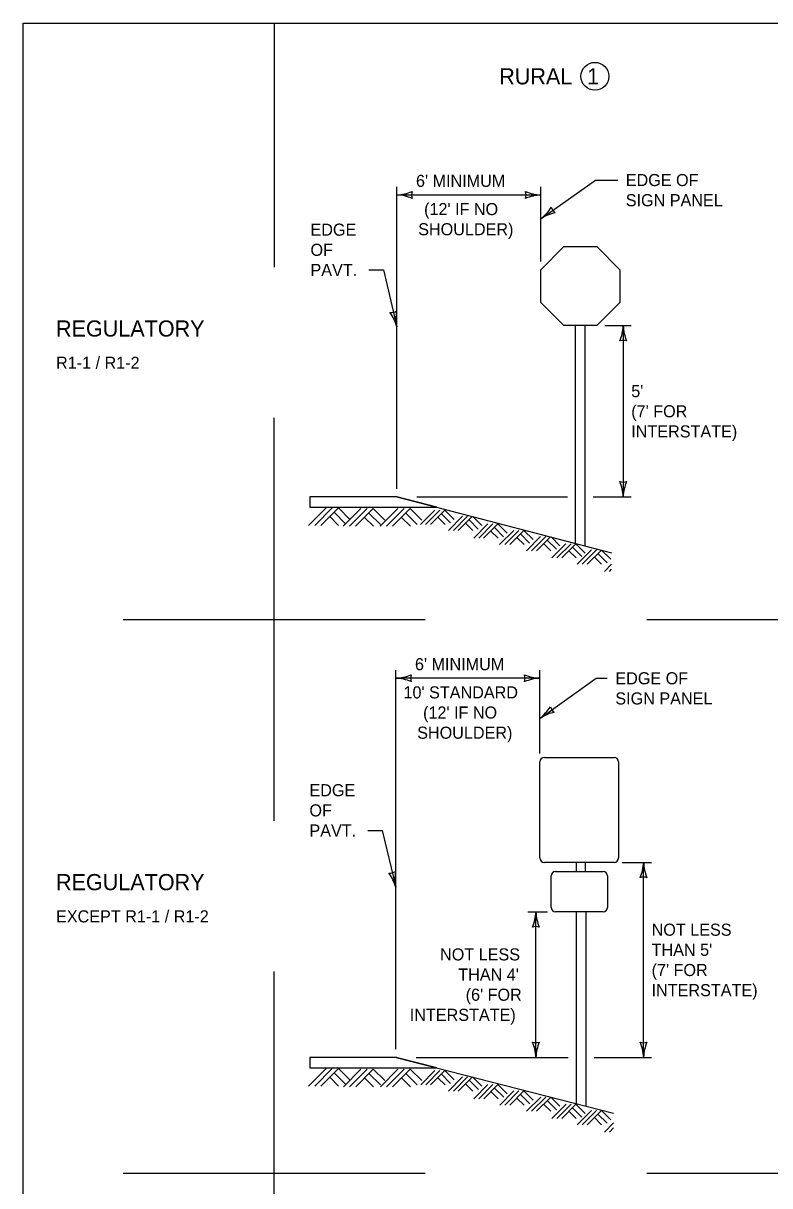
# Model space of a CAD drawing. Extents: x 49991.4 to 50021, y 49987.6 to 50011.4.
# Drawn here: x 49999.38 to 50003.09, y 49993.23 to 49999 of the extents above; entities that cross this region are included whole.
import ezdxf

# ---------------------------------------------------------------- set-up
doc = ezdxf.new("R2010")
doc.units = 0
for name, color, linetype in [('Level 1', 7, 'Continuous'), ('Level 2', 7, 'Continuous'), ('Level 3', 7, 'Continuous')]:
    doc.layers.add(name, color=color, linetype=linetype)

msp = doc.modelspace()

# ---------------------------------------------------------------- linework, layer by layer
at = {"layer": 'Level 1'}
for p, q in [((50002.124, 49996.4185), (50002.124, 49997.4987)), ((50002.1727, 49996.4059), (50002.1727, 49997.4987)), ((50001.2375, 49996.649), (50000.8056, 49996.649)), ((50000.8056, 49996.649), (50000.8056, 49996.5973)), ((50001.2374, 49996.649), (50000.8056, 49996.649)), ((50000.8056, 49996.649), (50000.8056, 49996.5973)), ((50001.2374, 49996.649), (50002.3037, 49996.3718)), ((50001.4363, 49996.5973), (50001.2374, 49996.649)), ((50000.7994, 49996.5068), (50000.8867, 49996.5941)), ((50000.8056, 49996.5973), (50001.4363, 49996.5973)), ((50000.8056, 49996.5973), (50001.4363, 49996.5973)), ((50000.83, 49996.5068), (50000.9173, 49996.5941)), ((50000.8605, 49996.5068), (50000.9477, 49996.5941)), ((50000.9046, 49996.5508), (50000.9488, 49996.5068)), ((50000.9263, 49996.5725), (50000.983, 49996.5158)), ((50000.9477, 49996.5941), (50001.0046, 49996.5373)), ((50000.9721, 49996.5031), (50001.0594, 49996.5905)), ((50001.0027, 49996.5031), (50001.0901, 49996.5905)), ((50001.0332, 49996.5031), (50001.1206, 49996.5905)), ((50001.0774, 49996.5471), (50001.1215, 49996.5031)), ((50001.099, 49996.5688), (50001.1558, 49996.5122)), ((50001.1206, 49996.5905), (50001.1774, 49996.5336)), ((50001.1556, 49996.5031), (50001.2429, 49996.5905)), ((50001.1863, 49996.5031), (50001.2736, 49996.5905)), ((50001.2167, 49996.5031), (50001.3041, 49996.5905)), ((50001.2608, 49996.5471), (50001.305, 49996.5031)), ((50001.2825, 49996.5688), (50001.3393, 49996.5122)), ((50001.3041, 49996.5905), (50001.361, 49996.5336)), ((50001.3558, 49996.5125), (50001.4265, 49996.5833)), ((50001.3807, 49996.5125), (50001.4514, 49996.5833)), ((50001.4053, 49996.5125), (50001.4761, 49996.5833)), ((50001.4348, 49996.5977), (50001.4348, 49996.5973)), ((50001.4361, 49996.5973), (50001.4361, 49996.5973)), ((50001.4361, 49996.5973), (50001.4361, 49996.5973)), ((50001.4361, 49996.5973), (50001.4361, 49996.5973)), ((50001.4411, 49996.5483), (50001.4769, 49996.5125)), ((50001.4585, 49996.5659), (50001.5046, 49996.52)), ((50001.4761, 49996.5833), (50001.5222, 49996.5373)), ((50001.4933, 49996.4819), (50001.564, 49996.5527)), ((50001.5181, 49996.4819), (50001.5889, 49996.5527)), ((50001.5428, 49996.4819), (50001.6123, 49996.5515)), ((50001.6155, 49996.5507), (50001.6595, 49996.5067)), ((50001.5785, 49996.5176), (50001.6145, 49996.4819)), ((50001.5961, 49996.5352), (50001.642, 49996.4892)), ((50001.6191, 49996.4437), (50001.6898, 49996.5143)), ((50001.6439, 49996.4437), (50001.7145, 49996.5143)), ((50001.6684, 49996.4437), (50001.7392, 49996.5143)), ((50001.7218, 49996.497), (50001.7678, 49996.451)), ((50001.7392, 49996.5143), (50001.7853, 49996.4683)), ((50001.7043, 49996.4794), (50001.7401, 49996.4437)), ((50001.748, 49996.4117), (50001.8187, 49996.4826)), ((50001.773, 49996.4117), (50001.8438, 49996.4826)), ((50001.7977, 49996.4117), (50001.8684, 49996.4826)), ((50001.8334, 49996.4474), (50001.8692, 49996.4117)), ((50001.8509, 49996.4651), (50001.8969, 49996.4192)), ((50001.8684, 49996.4826), (50001.9145, 49996.4365)), ((50001.8808, 49996.3813), (50001.9515, 49996.4521)), ((50001.9057, 49996.3813), (50001.9765, 49996.4521)), ((50001.9304, 49996.3813), (50001.9999, 49996.4508)), ((50001.9837, 49996.4345), (50002.0296, 49996.3889)), ((50002.0035, 49996.4499), (50002.0473, 49996.4063)), ((50001.9662, 49996.417), (50002.0018, 49996.3813)), ((50002.0063, 49996.3456), (50002.077, 49996.4164)), ((50002.0314, 49996.3456), (50002.1021, 49996.4164)), ((50002.0559, 49996.3456), (50002.1266, 49996.4164)), ((50002.0916, 49996.3813), (50002.1274, 49996.3456)), ((50002.1091, 49996.3989), (50002.1552, 49996.3529)), ((50002.1266, 49996.4164), (50002.1728, 49996.3703)), ((50002.1327, 49996.3145), (50002.2033, 49996.3853)), ((50002.1575, 49996.3145), (50002.2283, 49996.3853)), ((50002.1821, 49996.3145), (50002.2527, 49996.3851)), ((50002.2533, 49996.3849), (50002.299, 49996.3393)), ((50002.2179, 49996.3502), (50002.2537, 49996.3145)), ((50002.2354, 49996.3677), (50002.2814, 49996.3219)), ((50002.268, 49996.2787), (50002.3037, 49996.3144)), ((50002.2929, 49996.2787), (50002.3037, 49996.2895)), ((50001.9475, 49994.8576), (50001.9475, 49995.3338)), ((50001.97, 49995.3563), (50002.3161, 49995.3563)), ((50002.3386, 49995.3338), (50002.3386, 49994.8576)), ((50002.3161, 49994.8351), (50001.97, 49994.8351)), ((50002.1286, 49994.7902), (50002.1286, 49994.8351)), ((50002.1748, 49994.7902), (50002.1748, 49994.8351)), ((50002.0036, 49994.611), (50002.0036, 49994.7687)), ((50002.0251, 49994.7902), (50002.2611, 49994.7902)), ((50002.2826, 49994.7687), (50002.2826, 49994.611)), ((50002.2611, 49994.5895), (50002.0251, 49994.5895)), ((50002.1286, 49993.6382), (50002.1286, 49994.5895)), ((50002.1286, 49993.637), (50002.1286, 49994.5895)), ((50002.1772, 49993.6257), (50002.1772, 49994.5895)), ((50002.1772, 49993.6243), (50002.1772, 49994.5895)), ((50001.2376, 49993.8673), (50000.8056, 49993.8673)), ((50000.8056, 49993.8673), (50000.8056, 49993.8156)), ((50001.2343, 49993.8673), (50000.8056, 49993.8673)), ((50000.8056, 49993.8673), (50000.8056, 49993.8156)), ((50001.2343, 49993.8673), (50002.3135, 49993.5908)), ((50001.4361, 49993.8156), (50001.2343, 49993.8673)), ((50000.7995, 49993.725), (50000.8868, 49993.8124)), ((50000.8056, 49993.8156), (50001.4362, 49993.8156)), ((50000.8056, 49993.8156), (50001.4361, 49993.8156)), ((50000.8301, 49993.725), (50000.9175, 49993.8124)), ((50000.8606, 49993.725), (50000.9479, 49993.8124)), ((50000.9264, 49993.7908), (50000.9832, 49993.7341)), ((50000.9479, 49993.8124), (50001.0048, 49993.7556)), ((50000.9723, 49993.7214), (50001.0596, 49993.8087)), ((50001.003, 49993.7214), (50001.0903, 49993.8087)), ((50001.0334, 49993.7214), (50001.1207, 49993.8087)), ((50001.0991, 49993.7871), (50001.1559, 49993.7305)), ((50001.1207, 49993.8087), (50001.1776, 49993.752)), ((50001.1558, 49993.7214), (50001.2431, 49993.8087)), ((50001.1865, 49993.7214), (50001.2738, 49993.8087)), ((50001.2169, 49993.7214), (50001.3042, 49993.8087)), ((50001.2826, 49993.7871), (50001.3394, 49993.7305)), ((50001.3042, 49993.8087), (50001.3611, 49993.752)), ((50001.356, 49993.7309), (50001.4267, 49993.8016)), ((50001.3809, 49993.7309), (50001.4516, 49993.8016)), ((50001.4055, 49993.7309), (50001.4762, 49993.8016)), ((50001.4362, 49993.8156), (50001.4362, 49993.8156)), ((50001.4587, 49993.7842), (50001.5048, 49993.7383)), ((50001.4762, 49993.8016), (50001.5223, 49993.7556)), ((50000.9047, 49993.7691), (50000.9489, 49993.725)), ((50001.0776, 49993.7654), (50001.1217, 49993.7214)), ((50001.2611, 49993.7654), (50001.3052, 49993.7214)), ((50001.4413, 49993.7666), (50001.4772, 49993.7309)), ((50001.4934, 49993.7002), (50001.5641, 49993.7709)), ((50001.5183, 49993.7002), (50001.589, 49993.7709)), ((50001.5429, 49993.7002), (50001.6131, 49993.7703)), ((50001.5787, 49993.7358), (50001.6146, 49993.7002)), ((50001.5963, 49993.7535), (50001.6422, 49993.7076)), ((50001.6148, 49993.7698), (50001.6597, 49993.7249)), ((50001.6192, 49993.6619), (50001.6899, 49993.7326)), ((50001.6441, 49993.6619), (50001.7148, 49993.7326)), ((50001.6687, 49993.6619), (50001.7394, 49993.7326)), ((50001.7394, 49993.7326), (50001.7855, 49993.6866)), ((50001.7045, 49993.6976), (50001.7402, 49993.6619)), ((50001.722, 49993.7152), (50001.768, 49993.6693)), ((50001.7482, 49993.6301), (50001.8189, 49993.7009)), ((50001.7732, 49993.6301), (50001.8439, 49993.7009)), ((50001.7978, 49993.6301), (50001.8685, 49993.7009)), ((50001.8336, 49993.6657), (50001.8694, 49993.6301)), ((50001.8511, 49993.6834), (50001.897, 49993.6375)), ((50001.8685, 49993.7009), (50001.9146, 49993.6548)), ((50001.881, 49993.5996), (50001.9517, 49993.6703)), ((50001.9059, 49993.5996), (50001.9767, 49993.6703)), ((50001.9306, 49993.5996), (50002.0013, 49993.6703)), ((50002.0013, 49993.6703), (50002.0474, 49993.6245)), ((50001.9664, 49993.6353), (50002.0021, 49993.5996)), ((50001.9839, 49993.6529), (50002.0298, 49993.6072)), ((50002.0066, 49993.5639), (50002.0773, 49993.6347)), ((50002.0315, 49993.5639), (50002.1023, 49993.6347)), ((50002.056, 49993.5639), (50002.1268, 49993.6347)), ((50002.1093, 49993.6172), (50002.1554, 49993.5713)), ((50002.1268, 49993.6347), (50002.173, 49993.5886)), ((50002.1328, 49993.5328), (50002.2035, 49993.6035)), ((50002.1577, 49993.5328), (50002.2285, 49993.6035)), ((50002.1823, 49993.5328), (50002.2531, 49993.6035)), ((50002.2531, 49993.6035), (50002.2992, 49993.5576)), ((50002.0918, 49993.5996), (50002.1276, 49993.5639)), ((50002.2182, 49993.5685), (50002.2539, 49993.5328)), ((50002.2357, 49993.5861), (50002.2816, 49993.5402)), ((50002.2682, 49993.4969), (50002.3135, 49993.5422)), ((50002.2931, 49993.4969), (50002.3135, 49993.5173))]:
    msp.add_line(p, q, dxfattribs=at)
for points in [[(49999.3835, 49998.9992), (50016.7501, 49998.9992), (50016.7501, 49987.7988), (49999.3835, 49987.7988)], [(50002.0669, 49997.8908), (50002.2297, 49997.8908), (50002.3444, 49997.7761), (50002.3444, 49997.6134), (50002.2297, 49997.4987), (50002.0669, 49997.4987), (50001.9523, 49997.6134), (50001.9523, 49997.7761)]]:
    msp.add_lwpolyline(points, close=True, dxfattribs=at)
for centre, radius, start, end in [((50001.97, 49995.3338), 0.0225, 90, 180), ((50002.3161, 49995.3338), 0.0225, 0, 90), ((50001.97, 49994.8576), 0.0225, 180, 270), ((50002.3161, 49994.8576), 0.0225, 270, 0), ((50002.0251, 49994.7687), 0.0215, 90, 180), ((50002.2611, 49994.7687), 0.0215, 0, 90), ((50002.0251, 49994.611), 0.0215, 180, 270), ((50002.2611, 49994.611), 0.0215, 270, 0)]:
    msp.add_arc(centre, radius, start, end, dxfattribs=at)
at = {"layer": 'Level 2'}
msp.add_circle((50002.2206, 49998.7359), 0.0693, dxfattribs=at)
at = {"layer": 'Level 3'}
for p, q in [((50000.6286, 49998.9992), (50000.6286, 49997.788)), ((50001.9523, 49998.0283), (50002.223, 49998.2211)), ((50002.223, 49998.2211), (50002.3338, 49998.2211)), ((50001.2375, 49996.689), (50001.2375, 49998.187)), ((50001.9523, 49997.8161), (50001.9523, 49998.187)), ((50001.2375, 49998.147), (50001.9523, 49998.147)), ((50001.0987, 49997.7749), (50001.1707, 49997.7749)), ((50001.1707, 49997.7749), (50001.2375, 49997.4934)), ((50002.2697, 49997.4987), (50002.4012, 49997.4987)), ((50002.3612, 49997.4987), (50002.3612, 49996.649)), ((50000.6286, 49995.0407), (50000.6286, 49997.0407)), ((50001.3374, 49996.649), (50002.084, 49996.649)), ((50002.2127, 49996.649), (50002.4012, 49996.649)), ((49999.8786, 49996.0407), (50001.3786, 49996.0407)), ((50002.4787, 49996.0407), (50003.9787, 49996.0407)), ((50001.2323, 49993.9073), (50001.2323, 49995.7886)), ((50001.9475, 49995.7486), (50001.2323, 49995.7486)), ((50001.9475, 49995.3751), (50001.9475, 49995.7886)), ((50001.9475, 49995.5496), (50002.2269, 49995.7486)), ((50002.2269, 49995.7486), (50002.2823, 49995.7486)), ((50001.0935, 49994.9932), (50001.1655, 49994.9932)), ((50001.1655, 49994.9932), (50001.2323, 49994.7117)), ((50002.3561, 49994.8351), (50002.5022, 49994.8351)), ((50002.4622, 49993.8669), (50002.4622, 49994.8351)), ((50001.888, 49994.5895), (50001.9851, 49994.5895)), ((50001.928, 49993.8673), (50001.928, 49994.5895)), ((50000.6286, 49992.2934), (50000.6286, 49994.2934)), ((50001.3343, 49993.8673), (50002.0886, 49993.8673)), ((50002.2172, 49993.8669), (50002.5022, 49993.8669)), ((49999.8786, 49993.2934), (50001.3786, 49993.2934)), ((50002.4787, 49993.2934), (50003.9787, 49993.2934))]:
    msp.add_line(p, q, dxfattribs=at)
for centre, radius, start, end in [((50001.226, 49998.3797), 0.233, 272.82731, 292.07716), ((50001.3657, 49998.147), 0.0548, 162.13882, 197.86118), ((50001.9615, 49998.3691), 0.2223, 247.45601, 267.63952), ((50001.8241, 49998.147), 0.0548, 342.13882, 17.86118), ((50001.2283, 49997.9249), 0.2223, 67.45601, 87.63952), ((50001.9638, 49997.9143), 0.233, 92.82731, 112.07716), ((50001.8079, 49998.2112), 0.233, 308.28683, 327.53668), ((50002.0737, 49997.8421), 0.2223, 102.91553, 123.09904), ((50002.0567, 49998.1027), 0.0548, 197.59834, 233.3207), ((50001.2079, 49997.6182), 0.0548, 265.4882, 301.21056), ((50001.0137, 49997.4285), 0.233, 16.17669, 35.42654), ((50001.4557, 49997.5358), 0.2223, 170.80539, 190.9889), ((50002.1391, 49997.5079), 0.2223, 337.45601, 357.63952), ((50002.5939, 49997.5102), 0.233, 182.82731, 202.07716), ((50002.3612, 49997.3705), 0.0548, 72.13882, 107.86118), ((50002.3612, 49996.7772), 0.0548, 252.13882, 287.86118), ((50002.1285, 49996.6375), 0.233, 2.82731, 22.07716), ((50002.5833, 49996.6398), 0.2223, 157.45601, 177.63952), ((50001.2208, 49995.9813), 0.233, 272.82731, 292.07716), ((50001.2231, 49995.5265), 0.2223, 67.45601, 87.63952), ((50001.3605, 49995.7486), 0.0548, 162.13882, 197.86118), ((50001.9567, 49995.9707), 0.2223, 247.45601, 267.63952), ((50001.8193, 49995.7486), 0.0548, 342.13882, 17.86118), ((50001.959, 49995.5159), 0.233, 92.82731, 112.07716), ((50001.8031, 49995.7325), 0.233, 308.28732, 327.53717), ((50002.0689, 49995.3634), 0.2223, 102.91602, 123.09953), ((50002.0519, 49995.624), 0.0548, 197.59883, 233.32119), ((50002.2401, 49994.8443), 0.2223, 337.45601, 357.63952), ((50002.6949, 49994.8466), 0.233, 182.82731, 202.07716), ((50001.2027, 49994.8365), 0.0548, 265.4882, 301.21056), ((50001.0085, 49994.6468), 0.233, 16.17669, 35.42654), ((50001.4505, 49994.7541), 0.2223, 170.80539, 190.9889), ((50002.4622, 49994.7069), 0.0548, 72.13882, 107.86118), ((50001.7059, 49994.5987), 0.2223, 337.45601, 357.63952), ((50002.1607, 49994.601), 0.233, 182.82731, 202.07716), ((50001.928, 49994.4613), 0.0548, 72.13882, 107.86118), ((50001.928, 49993.9955), 0.0548, 252.13882, 287.86118), ((50001.6953, 49993.8558), 0.233, 2.82731, 22.07716), ((50002.1501, 49993.8581), 0.2223, 157.45601, 177.63952), ((50002.4622, 49993.9951), 0.0548, 252.13882, 287.86118), ((50002.2295, 49993.8554), 0.233, 2.82731, 22.07716), ((50002.6843, 49993.8577), 0.2223, 157.45601, 177.63952)]:
    msp.add_arc(centre, radius, start, end, dxfattribs=at)

# ---------------------------------------------------------------- texts
at = {"layer": 'Level 2'}
for s, height, p in [('RURAL', 0.08, (50001.746, 49998.6959)), ('1', 0.08, (50002.1822, 49998.6958)), ("6' MINIMUM", 0.06, (50001.3327, 49998.187)), ('EDGE OF', 0.06, (50002.3738, 49998.1911)), ("(12' IF NO", 0.06, (50001.3729, 49998.047)), ('SIGN PANEL', 0.06, (50002.3738, 49998.0911)), ('EDGE', 0.06, (50000.8091, 49997.9449)), ('SHOULDER)', 0.06, (50001.3437, 49997.947)), ('OF', 0.06, (50000.8091, 49997.8449)), ('PAVT.', 0.06, (50000.8091, 49997.7449)), ('REGULATORY', 0.08, (49999.5462, 49997.4444)), ('R1-1 / R1-2', 0.06, (49999.5462, 49997.2844)), ("5'", 0.06, (50002.4012, 49997.1438)), ("(7' FOR", 0.06, (50002.4012, 49997.0438)), ('INTERSTATE)', 0.06, (50002.4012, 49996.9438)), ("6' MINIMUM", 0.06, (50001.3277, 49995.7886)), ('EDGE OF', 0.06, (50002.3223, 49995.7186)), ("10' STANDARD", 0.06, (50001.2708, 49995.6486)), ('SIGN PANEL', 0.06, (50002.3223, 49995.6186)), ("(12' IF NO", 0.06, (50001.3679, 49995.5486)), ('SHOULDER)', 0.06, (50001.3387, 49995.4486)), ('EDGE', 0.06, (50000.8039, 49995.1632)), ('OF', 0.06, (50000.8039, 49995.0632)), ('PAVT.', 0.06, (50000.8039, 49994.9632)), ('REGULATORY', 0.08, (49999.5462, 49994.6971)), ('EXCEPT R1-1 / R1-2', 0.06, (49999.5462, 49994.5371)), ('NOT LESS', 0.06, (50002.5022, 49994.471)), ('NOT LESS', 0.06, (50001.4523, 49994.3484)), ("THAN 5'", 0.06, (50002.5022, 49994.371)), ("THAN 4'", 0.06, (50001.5427, 49994.2484)), ("(7' FOR", 0.06, (50002.5022, 49994.271)), ("(6' FOR", 0.06, (50001.5793, 49994.1484)), ('INTERSTATE)', 0.06, (50002.5022, 49994.171)), ('INTERSTATE)', 0.06, (50001.3019, 49994.0484))]:
    msp.add_text(s, height=height, dxfattribs=at).set_placement(p)

doc.saveas('drawing.dxf')
